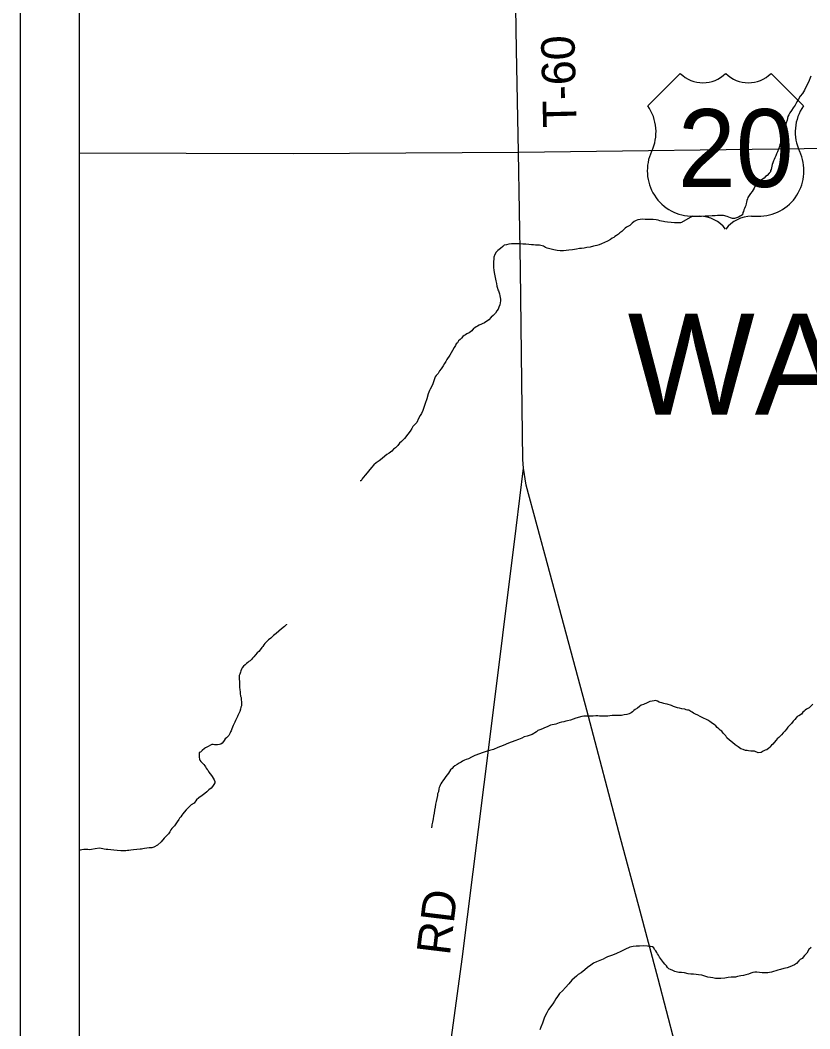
# Model space of a CAD drawing. Extents: x 0 to 34, y 0 to 22.
# Drawn here: x 2 to 3.337, y 16.386 to 18.093 of the extents above; entities that cross this region are included whole.
import ezdxf

# ---------------------------------------------------------------- set-up
doc = ezdxf.new("R2010")
doc.units = 0
for name, color, linetype in [('GM_X_Corporation', 7, 'Continuous'), ('GM_X_County_Road', 7, 'Continuous'), ('GM_X_County_Road_Text', 7, 'Continuous'), ('GM_X_Minor_River', 7, 'Continuous'), ('GM_X_Township_Road', 7, 'Continuous'), ('GM_X_Township_Road_Text', 7, 'Continuous'), ('GM_X_Township_Text', 7, 'Continuous'), ('GM_X_US_Location', 7, 'Continuous'), ('GM_X_US_Route', 7, 'Continuous'), ('GM_X_US_Shield', 7, 'Continuous'), ('SH_Data', 7, 'Continuous')]:
    doc.layers.add(name, color=color, linetype=linetype)

msp = doc.modelspace()

# ---------------------------------------------------------------- linework, layer by layer
at = {"layer": 'GM_X_Corporation'}
for points in [[(2.1, 20.3879), (2.1, 14.1)], [(2.1, 20.3879), (2.1, 15.3574)]]:
    msp.add_lwpolyline(points, dxfattribs=at)
at = {"layer": 'GM_X_County_Road'}
msp.add_lwpolyline([(2.6114, 15.3353), (2.6125, 15.3557), (2.613, 15.3586), (2.6211, 15.4109), (2.6332, 15.4885), (2.6352, 15.5106), (2.6362, 15.5391), (2.6358, 15.5923), (2.6347, 15.6162), (2.6345, 15.6549), (2.6354, 15.6694), (2.6399, 15.6987), (2.6639, 15.8643), (2.6992, 16.1326), (2.7288, 16.3587), (2.7486, 16.5041), (2.7949, 16.8713), (2.8402, 17.2336), (2.8523, 17.3349), (2.8513, 17.3497), (2.8493, 17.4814), (2.8475, 17.671), (2.8442, 17.8697)], dxfattribs=at)
at = {"layer": 'GM_X_Minor_River'}
for points in [[(3.339, 17.9984), (3.3351, 17.9885), (3.3323, 17.9832), (3.328, 17.9749), (3.3246, 17.9693), (3.3211, 17.9644), (3.318, 17.9595), (3.3153, 17.9549), (3.3122, 17.9493), (3.3091, 17.9448), (3.3063, 17.9406), (3.3036, 17.9365), (3.3017, 17.9331), (3.3001, 17.93), (3.2989, 17.9243), (3.2974, 17.9198), (3.2962, 17.9149), (3.2946, 17.9088), (3.2934, 17.9031), (3.2918, 17.8982), (3.2902, 17.8929), (3.2882, 17.8868), (3.2866, 17.8823), (3.2858, 17.8796), (3.2843, 17.8747), (3.2823, 17.8702), (3.2808, 17.8672), (3.2796, 17.8638), (3.278, 17.8603), (3.2768, 17.8577), (3.2757, 17.8551), (3.2749, 17.852), (3.2737, 17.849), (3.2729, 17.846), (3.2725, 17.8433), (3.2717, 17.8407), (3.2709, 17.8388), (3.2705, 17.8365), (3.2686, 17.8346), (3.2651, 17.8305), (3.262, 17.8286), (3.2597, 17.826), (3.2555, 17.823), (3.2528, 17.8219), (3.2513, 17.8192), (3.2478, 17.8147), (3.2444, 17.8117), (3.2428, 17.8087), (3.2397, 17.8034), (3.237, 17.8), (3.2323, 17.7932), (3.2319, 17.791), (3.2308, 17.7879), (3.23, 17.7853), (3.2296, 17.783), (3.2288, 17.7796), (3.228, 17.7773), (3.2268, 17.7747), (3.2256, 17.772), (3.2248, 17.7694), (3.2241, 17.7675), (3.2233, 17.7637), (3.2164, 17.76), (3.2095, 17.7578), (3.2065, 17.7574), (3.203, 17.759), (3.1974, 17.761), (3.1913, 17.7625), (3.1871, 17.7626), (3.1841, 17.7626), (3.1807, 17.7627), (3.1769, 17.7623), (3.1719, 17.762), (3.1662, 17.7613), (3.1601, 17.7614), (3.154, 17.7611), (3.1461, 17.7612), (3.1411, 17.7612), (3.1385, 17.7613), (3.1201, 17.7508), (3.1182, 17.7505), (3.1151, 17.7501), (3.1121, 17.7502), (3.1079, 17.7502), (3.1022, 17.7507), (3.0961, 17.7515)], [(3.0961, 17.7515), (3.092, 17.7519), (3.0893, 17.7524), (3.0863, 17.7531), (3.0832, 17.7539), (3.0802, 17.7547), (3.0768, 17.7555), (3.0722, 17.756), (3.0692, 17.756), (3.0662, 17.756), (3.0627, 17.7561), (3.0586, 17.7561), (3.054, 17.7562), (3.0498, 17.7559), (3.046, 17.7555), (3.043, 17.7544), (3.0399, 17.7526), (3.0364, 17.7499), (3.0322, 17.7458), (3.0269, 17.7432), (3.0245, 17.7413), (3.0215, 17.7383), (3.0188, 17.7357), (3.0157, 17.7335), (3.013, 17.7312), (3.01, 17.729), (3.0073, 17.7271), (3.0054, 17.7256), (3.0027, 17.7241), (2.9996, 17.7222), (2.9946, 17.7193), (2.9897, 17.717), (2.9847, 17.7148), (2.9805, 17.7133), (2.9763, 17.7119), (2.971, 17.7108), (2.9652, 17.7093), (2.9595, 17.7083), (2.955, 17.7076), (2.9508, 17.7069), (2.9473, 17.7069), (2.942, 17.7058), (2.9352, 17.7048), (2.9291, 17.7041), (2.9249, 17.7034), (2.9199, 17.7027), (2.9142, 17.7027), (2.9093, 17.7032), (2.9036, 17.7048), (2.8972, 17.7064), (2.8926, 17.7072), (2.8896, 17.7087), (2.8862, 17.7107), (2.882, 17.7119), (2.8794, 17.7123), (2.8771, 17.7127), (2.8748, 17.7127), (2.8729, 17.7127), (2.8695, 17.7128), (2.8657, 17.7132), (2.8615, 17.7136), (2.8562, 17.7141), (2.8513, 17.7141), (2.8459, 17.7146), (2.8406, 17.7146), (2.8364, 17.7147), (2.8323, 17.7147), (2.8277, 17.7144), (2.8235, 17.7133), (2.8197, 17.7122), (2.8174, 17.71), (2.8132, 17.7066), (2.8089, 17.7032), (2.8059, 17.7006), (2.8039, 17.6964), (2.8023, 17.6919), (2.8019, 17.6881), (2.8015, 17.6851), (2.8015, 17.6828), (2.8014, 17.679), (2.8018, 17.6771), (2.8017, 17.6744), (2.8021, 17.6702), (2.8028, 17.6664), (2.8035, 17.6634), (2.8039, 17.6603), (2.8057, 17.6519), (2.8064, 17.6474), (2.8074, 17.6432), (2.8082, 17.6397), (2.8089, 17.6371), (2.81, 17.6352), (2.8104, 17.6333), (2.8115, 17.6302), (2.8122, 17.6268), (2.8129, 17.6237), (2.8133, 17.6211), (2.8132, 17.618), (2.8124, 17.6112), (2.8108, 17.6074), (2.8093, 17.6044)], [(2.8093, 17.6044), (2.8073, 17.6014), (2.805, 17.5972), (2.8011, 17.5935), (2.7977, 17.5905), (2.7935, 17.5859), (2.7866, 17.5811), (2.7774, 17.577), (2.7743, 17.5755), (2.7724, 17.5744), (2.7697, 17.5725), (2.7678, 17.5714), (2.7651, 17.5673), (2.7605, 17.5639), (2.7567, 17.5624), (2.754, 17.5606), (2.7517, 17.5594), (2.7498, 17.5576), (2.7475, 17.5553), (2.7452, 17.5527), (2.7425, 17.5504), (2.7405, 17.5474), (2.7386, 17.5455), (2.7374, 17.5425), (2.7351, 17.5391), (2.732, 17.5342), (2.7301, 17.5304), (2.7274, 17.5263), (2.7227, 17.5187), (2.7208, 17.5153), (2.7188, 17.5123), (2.7161, 17.5082), (2.713, 17.5033), (2.7099, 17.4999), (2.7076, 17.495), (2.7045, 17.492), (2.703, 17.4897), (2.7006, 17.4829), (2.6986, 17.478), (2.6967, 17.4727), (2.6943, 17.4689), (2.6932, 17.4666), (2.6912, 17.4606), (2.6888, 17.4522), (2.6861, 17.4443), (2.6849, 17.4409), (2.6837, 17.4375), (2.6821, 17.4325), (2.6798, 17.4273), (2.6775, 17.4239), (2.6747, 17.419), (2.6716, 17.4125), (2.6674, 17.408), (2.6651, 17.4054), (2.6631, 17.402), (2.6604, 17.3978), (2.6566, 17.3926), (2.6511, 17.3854), (2.6458, 17.3801), (2.6423, 17.3775), (2.6396, 17.3734), (2.6354, 17.3692), (2.6323, 17.3674), (2.6292, 17.3636), (2.625, 17.3602), (2.6212, 17.3584), (2.6177, 17.3554), (2.6131, 17.3516), (2.6077, 17.3475), (2.6031, 17.3442), (2.5989, 17.3404), (2.5947, 17.3363), (2.585, 17.3235), (2.5808, 17.3193), (2.5789, 17.3167), (2.5773, 17.3137), (2.5762, 17.3133), (2.5758, 17.3133)], [(2.4508, 17.0711), (2.4508, 17.0704), (2.4474, 17.067), (2.4428, 17.0629), (2.4381, 17.0591), (2.4335, 17.0554), (2.4289, 17.0516), (2.4247, 17.0475), (2.4205, 17.0445), (2.4186, 17.0426), (2.4166, 17.0404), (2.4143, 17.0381), (2.4128, 17.0358), (2.4108, 17.0332), (2.4093, 17.0313), (2.4066, 17.0276), (2.4043, 17.0245), (2.4016, 17.0223), (2.3985, 17.0189), (2.3958, 17.0159), (2.3935, 17.0136), (2.3916, 17.0114), (2.3896, 17.0091), (2.3873, 17.0076), (2.3854, 17.0061), (2.3835, 17.0046), (2.3808, 17.002), (2.3781, 16.9998), (2.3758, 16.9971), (2.3746, 16.9949), (2.3739, 16.9922), (2.3731, 16.9899), (2.3719, 16.9862), (2.3711, 16.9839), (2.3711, 16.982), (2.371, 16.9797), (2.3713, 16.9721), (2.3713, 16.9683), (2.3716, 16.9641), (2.372, 16.9599), (2.3723, 16.9565), (2.3726, 16.9538), (2.3733, 16.9493), (2.3741, 16.9466), (2.3744, 16.9424), (2.3748, 16.9401), (2.3747, 16.9375), (2.3747, 16.9329), (2.3739, 16.9303), (2.3731, 16.9268), (2.3719, 16.9231), (2.3703, 16.9197), (2.3688, 16.9163), (2.368, 16.9144), (2.3664, 16.911), (2.3649, 16.9079), (2.3633, 16.9049), (2.3617, 16.9019), (2.3606, 16.8992), (2.3594, 16.8966), (2.3582, 16.8936), (2.3571, 16.8905), (2.3563, 16.8886), (2.3555, 16.8868), (2.3532, 16.8826), (2.3497, 16.8788), (2.3474, 16.877), (2.3454, 16.874), (2.3443, 16.8721), (2.342, 16.8694), (2.3397, 16.8679), (2.3374, 16.8672), (2.3343, 16.8665), (2.3313, 16.8665), (2.329, 16.8669), (2.3267, 16.867), (2.3248, 16.867), (2.316, 16.8629), (2.3141, 16.8614), (2.3122, 16.8603), (2.3084, 16.8569), (2.3053, 16.8543), (2.3034, 16.8535), (2.3029, 16.849), (2.3029, 16.8459), (2.3036, 16.8425), (2.3044, 16.8406), (2.3059, 16.8387), (2.3074, 16.8368), (2.3111, 16.8333), (2.3126, 16.8314), (2.3141, 16.8295), (2.3152, 16.8272), (2.3167, 16.8249), (2.3182, 16.823), (2.3193, 16.8207), (2.322, 16.8176), (2.3242, 16.8149), (2.3249, 16.813), (2.3268, 16.8103), (2.3287, 16.8072)], [(3.1922, 16.8848), (3.1903, 16.8867), (3.188, 16.8898), (3.1854, 16.8917), (3.1831, 16.8937), (3.1805, 16.896), (3.1779, 16.8987), (3.1752, 16.901), (3.1726, 16.9029), (3.1703, 16.9045), (3.1677, 16.9064), (3.1643, 16.9083), (3.1613, 16.9099), (3.1583, 16.9114), (3.1549, 16.913), (3.1518, 16.9149), (3.1477, 16.9169), (3.1435, 16.9188), (3.1405, 16.9204), (3.1379, 16.9219), (3.1356, 16.9231), (3.1326, 16.9251), (3.1303, 16.9255), (3.128, 16.9259), (3.1258, 16.927), (3.1208, 16.9279), (3.1163, 16.9287), (3.1129, 16.9295), (3.1098, 16.9303), (3.1064, 16.9318), (3.103, 16.933), (3.0955, 16.9354), (3.0924, 16.9362), (3.0898, 16.9366), (3.0867, 16.9378), (3.0841, 16.9386), (3.0822, 16.939), (3.0795, 16.9405), (3.0761, 16.9417), (3.0739, 16.9413), (3.07, 16.9406), (3.0662, 16.9399), (3.062, 16.9377), (3.0555, 16.9351), (3.0517, 16.9336), (3.049, 16.9317), (3.0452, 16.9287), (3.0414, 16.9265), (3.0391, 16.9246), (3.0371, 16.9228), (3.0348, 16.9209), (3.0314, 16.9194), (3.0272, 16.9183), (3.023, 16.9176), (3.0184, 16.9165), (3.0143, 16.9162), (3.0097, 16.9162), (3.0059, 16.9163), (3.0025, 16.9163), (2.9987, 16.916), (2.9952, 16.9153), (2.9922, 16.9153), (2.9872, 16.915), (2.9846, 16.915), (2.9812, 16.9154), (2.9785, 16.9155), (2.9751, 16.9155), (2.9705, 16.9152), (2.9652, 16.9153), (2.9603, 16.9153), (2.9568, 16.9154), (2.9546, 16.915), (2.9511, 16.9147), (2.9408, 16.9117), (2.9366, 16.9103), (2.9317, 16.9084), (2.9271, 16.9073), (2.924, 16.9066), (2.9206, 16.9055), (2.9168, 16.9048), (2.9126, 16.9037), (2.9069, 16.9019), (2.8981, 16.8997), (2.8924, 16.8971), (2.8878, 16.8956), (2.8844, 16.8938), (2.8802, 16.8919), (2.8767, 16.8908), (2.8744, 16.8886), (2.8668, 16.8841), (2.8584, 16.8812), (2.8534, 16.8801), (2.8496, 16.8782), (2.8442, 16.876), (2.8377, 16.8734), (2.827, 16.8694), (2.8182, 16.8653), (2.8091, 16.862), (2.8014, 16.859), (2.795, 16.8572), (2.7892, 16.8554)], [(3.3425, 16.9355), (3.336, 16.9295), (3.3318, 16.9269), (3.3295, 16.9254), (3.3276, 16.9239), (3.3257, 16.922), (3.323, 16.9186), (3.3184, 16.9156), (3.3161, 16.9145), (3.3141, 16.9126), (3.3118, 16.9096), (3.3091, 16.9066), (3.3064, 16.9028), (3.3033, 16.8998), (3.3003, 16.8965), (3.2976, 16.8931), (3.2952, 16.8901), (3.2922, 16.887), (3.2891, 16.8837), (3.2848, 16.8792), (3.2818, 16.8769), (3.2802, 16.8746), (3.2768, 16.8705), (3.2744, 16.8679), (3.2725, 16.866), (3.2698, 16.863), (3.2679, 16.8611), (3.2645, 16.8585), (3.2618, 16.8578), (3.258, 16.8559), (3.2549, 16.8537), (3.2499, 16.8533), (3.2435, 16.8557), (3.2374, 16.8561), (3.2336, 16.8566), (3.231, 16.857), (3.2283, 16.857), (3.2242, 16.8586), (3.2204, 16.8601), (3.2162, 16.8632), (3.211, 16.8667), (3.2061, 16.8706), (3.2012, 16.8744), (3.197, 16.8783), (3.1948, 16.8821), (3.1922, 16.8848)], [(2.7892, 16.8554), (2.7839, 16.8539), (2.7698, 16.8488), (2.7644, 16.8458), (2.7594, 16.8432), (2.7552, 16.8421), (2.7526, 16.8406), (2.7491, 16.8391), (2.7468, 16.8376), (2.7434, 16.8354), (2.7399, 16.8335), (2.7361, 16.8309), (2.7334, 16.8291), (2.7315, 16.8264), (2.7288, 16.8242), (2.7253, 16.8189), (2.723, 16.8159), (2.7211, 16.8132), (2.7187, 16.8095), (2.716, 16.8057), (2.7141, 16.8034), (2.7125, 16.8004), (2.7114, 16.7985), (2.7106, 16.7966), (2.7098, 16.7947), (2.709, 16.7921), (2.7082, 16.7872), (2.707, 16.7838), (2.7066, 16.7807), (2.7054, 16.7758), (2.7046, 16.7705), (2.7034, 16.7663), (2.7026, 16.7614), (2.7017, 16.7561), (2.7009, 16.7511), (2.7001, 16.7462), (2.6993, 16.7413), (2.6985, 16.736), (2.6973, 16.7314), (2.6969, 16.7284), (2.6965, 16.7272), (2.6964, 16.7261)], [(2.3287, 16.8072), (2.3298, 16.8046), (2.3294, 16.8023), (2.3278, 16.7993), (2.3259, 16.7963), (2.3232, 16.7933), (2.3197, 16.7903), (2.3163, 16.7872), (2.3128, 16.7842), (2.3082, 16.7809), (2.3028, 16.7768), (2.2986, 16.7734), (2.2948, 16.7681), (2.2898, 16.7651), (2.2813, 16.7569), (2.2778, 16.7527), (2.2755, 16.7497), (2.274, 16.7478), (2.272, 16.7448), (2.2701, 16.7426), (2.2686, 16.7403), (2.2659, 16.7365), (2.2639, 16.7331), (2.2612, 16.7297), (2.2589, 16.7271), (2.257, 16.7249), (2.2554, 16.7226), (2.2535, 16.7196), (2.2512, 16.7162), (2.2485, 16.7132), (2.2466, 16.7117), (2.2439, 16.7087), (2.2388, 16.7026), (2.2327, 16.697), (2.2266, 16.6933), (2.2231, 16.6922), (2.2186, 16.6922), (2.2144, 16.6919), (2.2106, 16.6912), (2.2079, 16.6908), (2.2052, 16.6901), (2.2033, 16.6901), (2.1973, 16.6898), (2.1919, 16.6891), (2.1874, 16.6884), (2.1839, 16.6881), (2.182, 16.6881), (2.179, 16.6874), (2.1752, 16.6871), (2.1702, 16.6871), (2.1645, 16.6876), (2.1585, 16.6884), (2.1482, 16.6897), (2.1456, 16.6897), (2.1425, 16.6901), (2.1402, 16.6909), (2.1346, 16.6917), (2.1269, 16.6907), (2.1208, 16.6896), (2.1182, 16.6892), (2.1148, 16.6893), (2.1113, 16.6893), (2.1079, 16.6894), (2.1045, 16.689), (2.1014, 16.6883), (2.1, 16.6878)], [(3.0745, 16.5205), (3.073, 16.5232), (3.0711, 16.5247), (3.0677, 16.5255), (3.0624, 16.526), (3.0556, 16.5265), (3.0491, 16.5261), (3.0434, 16.5258), (3.0381, 16.5255), (3.0327, 16.5241), (3.0239, 16.5204), (3.0171, 16.517), (3.0098, 16.5133), (3.0033, 16.5107), (2.9983, 16.5089), (2.9949, 16.5078), (2.9915, 16.5063), (2.9873, 16.5041), (2.9815, 16.5019), (2.9762, 16.4996), (2.9712, 16.4974), (2.9666, 16.4937), (2.9609, 16.4899), (2.9562, 16.4858), (2.9501, 16.4809), (2.9451, 16.478), (2.9421, 16.4753), (2.9386, 16.4723), (2.9344, 16.4682), (2.9293, 16.4622), (2.9236, 16.4558), (2.9182, 16.4502), (2.9136, 16.4457), (2.9097, 16.4408), (2.907, 16.4366), (2.9047, 16.4328), (2.9023, 16.4283), (2.895, 16.4189), (2.8934, 16.4166), (2.8919, 16.4132), (2.8896, 16.4091), (2.8872, 16.4041), (2.8848, 16.3958), (2.8817, 16.389), (2.8798, 16.3845)], [(3.3395, 16.5238), (3.3357, 16.5205), (3.3322, 16.514), (3.3283, 16.5099), (3.3244, 16.505), (3.321, 16.5032), (3.3187, 16.5009), (3.3148, 16.4968), (3.3114, 16.4945), (3.3076, 16.4927), (3.3034, 16.4908), (3.2988, 16.4894), (3.2931, 16.4879), (3.2877, 16.4864), (3.2832, 16.4854), (3.2725, 16.4821), (3.2687, 16.4814), (3.266, 16.481), (3.263, 16.4807), (3.2592, 16.4807), (3.2565, 16.4807), (3.2519, 16.4815), (3.2478, 16.482), (3.244, 16.482), (3.2405, 16.4813), (3.2371, 16.4802), (3.2333, 16.4787), (3.2291, 16.4773), (3.2249, 16.4762), (3.2207, 16.4755), (3.2176, 16.4751), (3.215, 16.4748), (3.2115, 16.4737), (3.2043, 16.4734), (3.199, 16.4727), (3.1933, 16.4716), (3.1868, 16.4709), (3.1819, 16.471), (3.1773, 16.4714), (3.1728, 16.4722), (3.169, 16.4726), (3.1644, 16.4735), (3.1595, 16.475), (3.1546, 16.4766), (3.1485, 16.4775), (3.1447, 16.4779), (3.1405, 16.4783), (3.136, 16.4784), (3.131, 16.4792), (3.1253, 16.4808), (3.12, 16.4812), (3.1155, 16.4816), (3.1132, 16.4821), (3.1109, 16.4825), (3.1086, 16.4832), (3.1052, 16.4848), (3.1011, 16.4864), (3.0984, 16.4876), (3.0962, 16.4899), (3.0943, 16.4925), (3.0917, 16.4956), (3.0894, 16.4983), (3.0827, 16.5075), (3.0808, 16.5106), (3.0794, 16.5132), (3.0782, 16.5152), (3.0767, 16.5178), (3.0745, 16.5205)]]:
    msp.add_lwpolyline(points, dxfattribs=at)
at = {"layer": 'GM_X_Township_Road'}
for points in [[(2.8442, 17.8697), (2.8403, 18.0431), (2.8371, 18.2593), (2.8342, 18.5466), (2.8299, 18.8735)], [(3.1744, 16.1479), (3.158, 16.1914), (3.1084, 16.3621), (3.0805, 16.4705), (3.0476, 16.5935), (3.0168, 16.7089), (2.9594, 16.9253), (2.8939, 17.1686), (2.857, 17.3063), (2.8523, 17.3349)]]:
    msp.add_lwpolyline(points, dxfattribs=at)
at = {"layer": 'GM_X_US_Route'}
msp.add_lwpolyline([(2.1, 17.869), (2.4623, 17.8676), (2.8442, 17.8697), (3.3716, 17.8767), (3.3868, 17.8768)], dxfattribs=at)
at = {"layer": 'GM_X_US_Shield'}
for p, q in [((3.1178, 18.0032), (3.0629, 17.9482)), ((3.3266, 17.9482), (3.2716, 18.0032)), ((3.1398, 17.7615), (3.1508, 17.7615)), ((3.2387, 17.7615), (3.2496, 17.7615))]:
    msp.add_line(p, q, dxfattribs=at)
for centre, radius, start, end in [((3.1563, 18.0424), 0.0549, 225.573, 314.427), ((3.2332, 18.0424), 0.0549, 225.573, 314.427), ((2.9999, 17.9041), 0.0769, 334.5471, 35.0009), ((3.3895, 17.9041), 0.0769, 144.9991, 205.4529), ((3.1389, 17.8384), 0.0769, 154.8319, 270.6383), ((3.2505, 17.8384), 0.0769, 269.3617, 25.1681), ((3.1508, 17.7065), 0.0549, 36.8699, 90), ((3.2387, 17.7065), 0.0549, 90, 143.1301)]:
    msp.add_arc(centre, radius, start, end, dxfattribs=at)
at = {"layer": 'SH_Data'}
for p, q in [((2, 21), (2, 14)), ((2.1, 20.9), (2.1, 14.1))]:
    msp.add_line(p, q, dxfattribs=at)

# ---------------------------------------------------------------- texts
at = {"layer": 'GM_X_County_Road_Text'}
msp.add_text('RD', height=0.05682, rotation=83.0591, dxfattribs=at).set_placement((2.7275, 16.509))
at = {"layer": 'GM_X_Township_Road_Text'}
msp.add_text('T-60', height=0.05682, rotation=91.4072, dxfattribs=at).set_placement((2.9425, 17.9121))
at = {"layer": 'GM_X_Township_Text'}
msp.add_text('WAKEMAN', height=0.17045, rotation=0, dxfattribs=at).set_placement((3.0289, 17.4258))
at = {"layer": 'GM_X_US_Location'}
for s, p in [('0', (3.1946, 17.8758)), ('/', (3.1947, 17.8758))]:
    msp.add_text(s, height=0.000189, dxfattribs=at).set_placement(p)
msp.add_text('20', height=0.000189, rotation=0, dxfattribs=at).set_placement((3.1556, 17.8366))
at = {"layer": 'GM_X_US_Shield'}
msp.add_text('20', height=0.13184, dxfattribs=at).set_placement((3.1138, 17.8109))

doc.saveas('drawing.dxf')
